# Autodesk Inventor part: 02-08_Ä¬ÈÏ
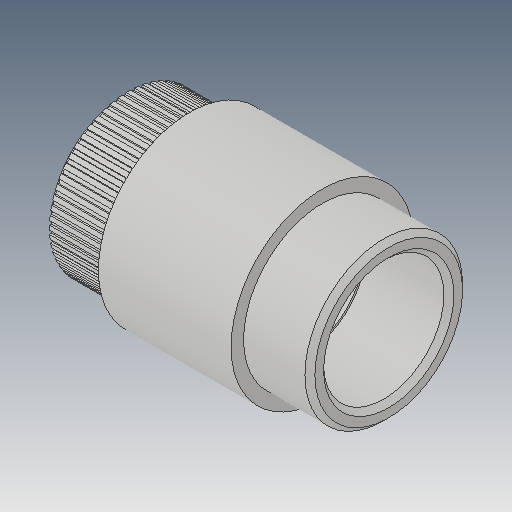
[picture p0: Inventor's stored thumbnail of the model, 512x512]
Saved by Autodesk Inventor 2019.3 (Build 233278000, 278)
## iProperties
Created: 2010-06
Part Number: 02-08_Ä¬ÈÏ
Material: Ogólny
Document SubType Name: Modeling
Designer: CADENGINEERING4
Density: 1 g/cm^3
Appearance: Domyślna
Author: CADENGINEERING4
Revision Number: ÈÎºÎ
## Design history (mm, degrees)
feature "NONE"
node "Bryła1"
